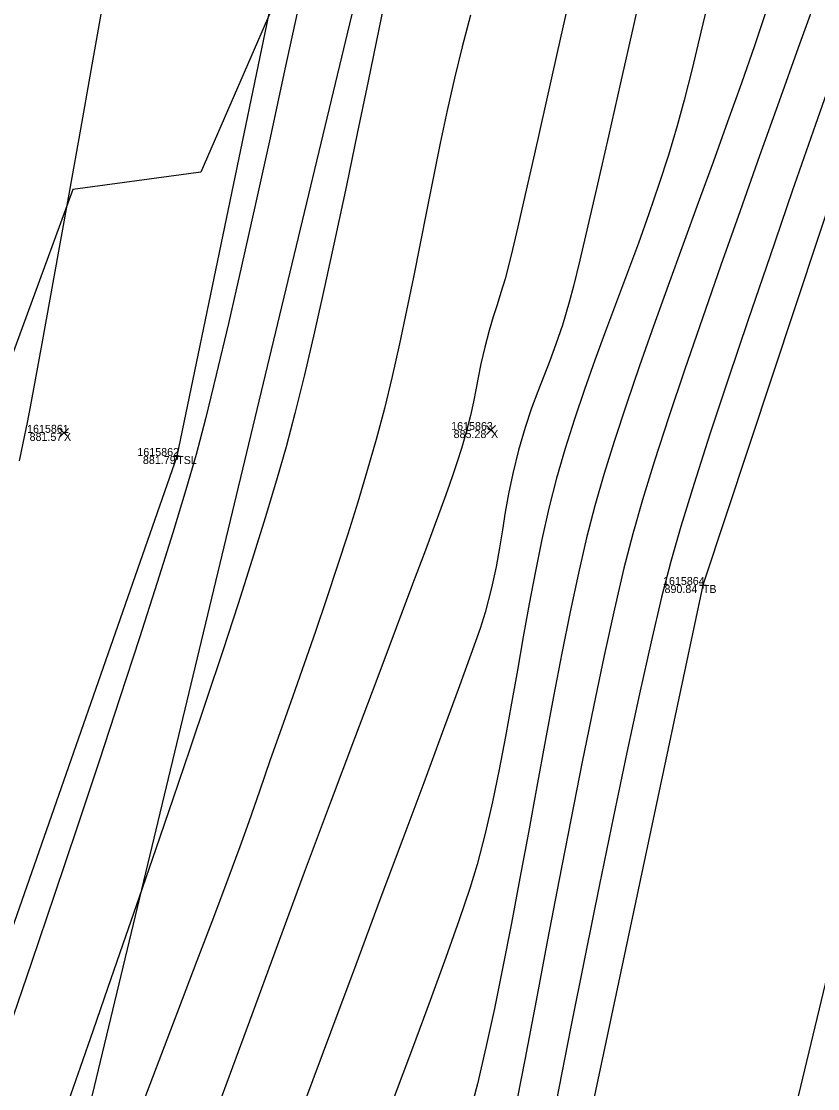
# Model space of a CAD drawing. Extents: x 1957117 to 1971063, y 701601 to 715861.
# Drawn here: x 1963015.01 to 1963049.81, y 704899.84 to 704946.5 of the extents above; entities that cross this region are included whole.
import ezdxf

# ---------------------------------------------------------------- set-up
doc = ezdxf.new("R2010")
doc.units = 0
for name, color, linetype in [('AP_X_Lights', 7, 'Continuous'), ('DT_X_Break_Line', 7, 'Continuous'), ('DT_X_Contour_Major', 7, 'Continuous'), ('DT_X_Contour_Minor', 7, 'Continuous'), ('GE_X_CL_20', 7, 'Continuous'), ('HY_X_Water_Edge', 7, 'Continuous'), ('PV_P_Drive', 7, 'Continuous'), ('PV_P_Shoulder', 7, 'Continuous'), ('RS_Raster1', 7, 'Continuous'), ('RW_X_Esmt_RR', 7, 'Continuous'), ('SC_Scratch1', 7, 'Continuous'), ('SC_Shading5', 7, 'Continuous'), ('VG_X_Tree_Line_Rt', 7, 'Continuous')]:
    doc.layers.add(name, color=color, linetype=linetype)

msp = doc.modelspace()

# ---------------------------------------------------------------- linework, layer by layer
at = {"layer": 'AP_X_Lights'}
for p, q in [((1963035.344, 704928.437), (1963035.732, 704928.827)), ((1963035.344, 704928.827), (1963035.732, 704928.437)), ((1963016.679, 704928.315), (1963017.067, 704928.705)), ((1963016.679, 704928.705), (1963017.067, 704928.315))]:
    msp.add_line(p, q, dxfattribs=at)
at = {"layer": 'DT_X_Break_Line'}
for points in [[(1962854.549, 704243.654), (1962868.069, 704295.231), (1962879.669, 704344.313), (1962892.757, 704392.318), (1962905.964, 704443.142), (1962917.718, 704492.375), (1962926.962, 704538.336), (1962936.778, 704587.265), (1962949.215, 704630.669), (1962963.968, 704683.754), (1962972.038, 704733.348), (1962988.206, 704780.999), (1962994.689, 704830.943), (1963004.932, 704879.138), (1963021.822, 704927.498), (1963031.944, 704976.286), (1963045.21, 705027.355), (1963059.618, 705072.384), (1963067.267, 705121.949)], [(1963081.686, 705067.168), (1963070.617, 705018.992), (1963060.629, 704969.66), (1963044.793, 704921.859), (1963033.624, 704869.219), (1963022.038, 704824.561), (1963012.554, 704778.141), (1962998.858, 704727.004), (1962987.967, 704677.611), (1962975.675, 704626.305), (1962966.447, 704580.213), (1962950.262, 704533.092), (1962939.515, 704481.257), (1962926.044, 704436.037), (1962917.68, 704386.811), (1962906.11, 704337.415), (1962892.064, 704289.931), (1962881.011, 704234.451)]]:
    msp.add_lwpolyline(points, dxfattribs=at)
at = {"layer": 'DT_X_Contour_Major'}
for points in [[(1963038.998, 704947.677), (1963038.428, 704945.137), (1963037.902, 704942.798), (1963037.432, 704940.713), (1963037.029, 704938.936), (1963036.706, 704937.52), (1963036.475, 704936.52), (1963036.348, 704935.989), (1963036.148, 704935.246), (1963035.969, 704934.641), (1963035.801, 704934.108), (1963035.635, 704933.578), (1963035.459, 704932.983), (1963035.265, 704932.255), (1963035.091, 704931.525), (1963034.969, 704930.927), (1963034.87, 704930.395), (1963034.769, 704929.864), (1963034.639, 704929.268), (1963034.452, 704928.542), (1963034.246, 704927.821), (1963034.063, 704927.239), (1963033.888, 704926.726), (1963033.705, 704926.215), (1963033.497, 704925.638), (1963033.248, 704924.928), (1963033.059, 704924.414), (1963032.673, 704923.385), (1963032.111, 704921.893), (1963031.392, 704919.99), (1963030.539, 704917.726), (1963029.571, 704915.152), (1963028.51, 704912.321), (1963027.376, 704909.284), (1963026.191, 704906.091), (1963024.975, 704902.795), (1963023.749, 704899.446)], [(1963038.998, 704947.677), (1963038.428, 704945.137), (1963037.902, 704942.798), (1963037.432, 704940.713), (1963037.029, 704938.936), (1963036.706, 704937.52), (1963036.475, 704936.52), (1963036.348, 704935.989), (1963036.148, 704935.246), (1963035.969, 704934.641), (1963035.801, 704934.108), (1963035.635, 704933.578), (1963035.459, 704932.983), (1963035.265, 704932.255), (1963035.091, 704931.525), (1963034.969, 704930.927), (1963034.87, 704930.395), (1963034.769, 704929.864), (1963034.639, 704929.268), (1963034.452, 704928.542), (1963034.246, 704927.821), (1963034.063, 704927.239), (1963033.888, 704926.726), (1963033.705, 704926.215), (1963033.497, 704925.638), (1963033.248, 704924.928), (1963033.059, 704924.414), (1963032.673, 704923.385), (1963032.111, 704921.893), (1963031.392, 704919.99), (1963030.539, 704917.726), (1963029.571, 704915.152), (1963028.51, 704912.321), (1963027.376, 704909.284), (1963026.191, 704906.091), (1963024.975, 704902.795), (1963023.749, 704899.446)], [(1963050.748, 704944.928), (1963049.719, 704941.992), (1963048.702, 704939.071), (1963047.715, 704936.211), (1963046.775, 704933.457), (1963045.899, 704930.856), (1963045.105, 704928.452), (1963044.411, 704926.292), (1963043.834, 704924.421), (1963043.392, 704922.885), (1963042.99, 704921.322), (1963042.53, 704919.376), (1963042.021, 704917.097), (1963041.469, 704914.535), (1963040.885, 704911.741), (1963040.275, 704908.766), (1963039.648, 704905.66), (1963039.013, 704902.474), (1963038.379, 704899.258)], [(1963050.748, 704944.928), (1963049.719, 704941.992), (1963048.702, 704939.071), (1963047.715, 704936.211), (1963046.775, 704933.457), (1963045.899, 704930.856), (1963045.105, 704928.452), (1963044.411, 704926.292), (1963043.834, 704924.421), (1963043.392, 704922.885), (1963042.99, 704921.322), (1963042.53, 704919.376), (1963042.021, 704917.097), (1963041.469, 704914.535), (1963040.885, 704911.741), (1963040.275, 704908.766), (1963039.648, 704905.66), (1963039.013, 704902.474), (1963038.379, 704899.258)]]:
    msp.add_lwpolyline(points, dxfattribs=at)
at = {"layer": 'DT_X_Contour_Minor'}
for points in [[(1963042.348, 704948.975), (1963041.756, 704946.324), (1963041.191, 704943.809), (1963040.665, 704941.479), (1963040.186, 704939.379), (1963039.765, 704937.556), (1963039.413, 704936.058), (1963039.14, 704934.93), (1963038.955, 704934.22), (1963038.657, 704933.224), (1963038.375, 704932.389), (1963038.104, 704931.662), (1963037.84, 704930.987), (1963037.576, 704930.313), (1963037.308, 704929.585), (1963037.032, 704928.749), (1963036.742, 704927.751), (1963036.485, 704926.734), (1963036.298, 704925.844), (1963036.156, 704925.037), (1963036.035, 704924.267), (1963035.911, 704923.489), (1963035.76, 704922.659), (1963035.558, 704921.73), (1963035.281, 704920.657), (1963035.058, 704919.959), (1963034.658, 704918.82), (1963034.102, 704917.285), (1963033.407, 704915.401), (1963032.593, 704913.211), (1963031.678, 704910.761), (1963030.681, 704908.095), (1963029.622, 704905.259), (1963028.518, 704902.298), (1963027.39, 704899.256)], [(1963042.348, 704948.975), (1963041.756, 704946.324), (1963041.191, 704943.809), (1963040.665, 704941.479), (1963040.186, 704939.379), (1963039.765, 704937.556), (1963039.413, 704936.058), (1963039.14, 704934.93), (1963038.955, 704934.22), (1963038.657, 704933.224), (1963038.375, 704932.389), (1963038.104, 704931.662), (1963037.84, 704930.987), (1963037.576, 704930.313), (1963037.308, 704929.585), (1963037.032, 704928.749), (1963036.742, 704927.751), (1963036.485, 704926.734), (1963036.298, 704925.844), (1963036.156, 704925.037), (1963036.035, 704924.267), (1963035.911, 704923.489), (1963035.76, 704922.659), (1963035.558, 704921.73), (1963035.281, 704920.657), (1963035.058, 704919.959), (1963034.658, 704918.82), (1963034.102, 704917.285), (1963033.407, 704915.401), (1963032.593, 704913.211), (1963031.678, 704910.761), (1963030.681, 704908.095), (1963029.622, 704905.259), (1963028.518, 704902.298), (1963027.39, 704899.256)], [(1963031.088, 704948.367), (1963030.633, 704946.157), (1963030.166, 704943.89), (1963029.691, 704941.602), (1963029.214, 704939.328), (1963028.74, 704937.1), (1963028.273, 704934.956), (1963027.819, 704932.928), (1963027.383, 704931.051), (1963026.969, 704929.361), (1963026.583, 704927.892), (1963026.168, 704926.437), (1963025.671, 704924.789), (1963025.105, 704922.976), (1963024.48, 704921.029), (1963023.809, 704918.978), (1963023.103, 704916.853), (1963022.374, 704914.683), (1963021.632, 704912.499), (1963020.89, 704910.33), (1963020.159, 704908.206), (1963019.451, 704906.157), (1963018.776, 704904.214), (1963018.147, 704902.405), (1963017.576, 704900.761), (1963017.073, 704899.312)], [(1963031.088, 704948.367), (1963030.633, 704946.157), (1963030.166, 704943.89), (1963029.691, 704941.602), (1963029.214, 704939.328), (1963028.74, 704937.1), (1963028.273, 704934.956), (1963027.819, 704932.928), (1963027.383, 704931.051), (1963026.969, 704929.361), (1963026.583, 704927.892), (1963026.168, 704926.437), (1963025.671, 704924.789), (1963025.105, 704922.976), (1963024.48, 704921.029), (1963023.809, 704918.978), (1963023.103, 704916.853), (1963022.374, 704914.683), (1963021.632, 704912.499), (1963020.89, 704910.33), (1963020.159, 704908.206), (1963019.451, 704906.157), (1963018.776, 704904.214), (1963018.147, 704902.405), (1963017.576, 704900.761), (1963017.073, 704899.312)], [(1963027.192, 704947.483), (1963026.532, 704944.41), (1963025.879, 704941.405), (1963025.243, 704938.517), (1963024.634, 704935.796), (1963024.06, 704933.29), (1963023.532, 704931.051), (1963023.058, 704929.126), (1963022.648, 704927.566), (1963022.205, 704926.021), (1963021.634, 704924.14), (1963020.952, 704921.967), (1963020.176, 704919.548), (1963019.322, 704916.929), (1963018.406, 704914.155), (1963017.445, 704911.272), (1963016.456, 704908.324), (1963015.454, 704905.358), (1963014.455, 704902.419), (1963013.477, 704899.551)], [(1963027.192, 704947.483), (1963026.532, 704944.41), (1963025.879, 704941.405), (1963025.243, 704938.517), (1963024.634, 704935.796), (1963024.06, 704933.29), (1963023.532, 704931.051), (1963023.058, 704929.126), (1963022.648, 704927.566), (1963022.205, 704926.021), (1963021.634, 704924.14), (1963020.952, 704921.967), (1963020.176, 704919.548), (1963019.322, 704916.929), (1963018.406, 704914.155), (1963017.445, 704911.272), (1963016.456, 704908.324), (1963015.454, 704905.358), (1963014.455, 704902.419), (1963013.477, 704899.551)], [(1963014.937, 704927.292), (1963015.096, 704928.056), (1963015.279, 704928.959), (1963015.412, 704929.655), (1963015.628, 704930.825), (1963015.917, 704932.413), (1963016.269, 704934.36), (1963016.675, 704936.61), (1963017.123, 704939.105), (1963017.604, 704941.788), (1963018.107, 704944.601), (1963018.623, 704947.488)], [(1963014.937, 704927.292), (1963015.096, 704928.056), (1963015.279, 704928.959), (1963015.412, 704929.655), (1963015.628, 704930.825), (1963015.917, 704932.413), (1963016.269, 704934.36), (1963016.675, 704936.61), (1963017.123, 704939.105), (1963017.604, 704941.788), (1963018.107, 704944.601), (1963018.623, 704947.488)], [(1963045.126, 704947.812), (1963044.706, 704946.02), (1963044.32, 704944.421), (1963043.974, 704943.049), (1963043.675, 704941.938), (1963043.293, 704940.647), (1963042.877, 704939.361), (1963042.436, 704938.078), (1963041.976, 704936.797), (1963041.503, 704935.518), (1963041.024, 704934.239), (1963040.546, 704932.961), (1963040.075, 704931.681), (1963039.619, 704930.399), (1963039.184, 704929.115), (1963038.777, 704927.827), (1963038.404, 704926.535), (1963038.067, 704925.216), (1963037.759, 704923.854), (1963037.473, 704922.458), (1963037.204, 704921.036), (1963036.945, 704919.594), (1963036.691, 704918.142), (1963036.436, 704916.686), (1963036.173, 704915.236), (1963035.896, 704913.799), (1963035.6, 704912.382), (1963035.279, 704910.994), (1963034.926, 704909.643), (1963034.604, 704908.587), (1963034.143, 704907.22), (1963033.561, 704905.578), (1963032.874, 704903.698), (1963032.101, 704901.618), (1963031.258, 704899.374)], [(1963045.126, 704947.812), (1963044.706, 704946.02), (1963044.32, 704944.421), (1963043.974, 704943.049), (1963043.675, 704941.938), (1963043.293, 704940.647), (1963042.877, 704939.361), (1963042.436, 704938.078), (1963041.976, 704936.797), (1963041.503, 704935.518), (1963041.024, 704934.239), (1963040.546, 704932.961), (1963040.075, 704931.681), (1963039.619, 704930.399), (1963039.184, 704929.115), (1963038.777, 704927.827), (1963038.404, 704926.535), (1963038.067, 704925.216), (1963037.759, 704923.854), (1963037.473, 704922.458), (1963037.204, 704921.036), (1963036.945, 704919.594), (1963036.691, 704918.142), (1963036.436, 704916.686), (1963036.173, 704915.236), (1963035.896, 704913.799), (1963035.6, 704912.382), (1963035.279, 704910.994), (1963034.926, 704909.643), (1963034.604, 704908.587), (1963034.143, 704907.22), (1963033.561, 704905.578), (1963032.874, 704903.698), (1963032.101, 704901.618), (1963031.258, 704899.374)], [(1963049.772, 704947.603), (1963048.964, 704945.346), (1963048.126, 704943.004), (1963047.273, 704940.615), (1963046.419, 704938.214), (1963045.581, 704935.837), (1963044.773, 704933.521), (1963044.011, 704931.3), (1963043.311, 704929.212), (1963042.687, 704927.292), (1963042.154, 704925.577), (1963041.729, 704924.101), (1963041.344, 704922.6), (1963040.926, 704920.81), (1963040.479, 704918.773), (1963040.01, 704916.532), (1963039.523, 704914.126), (1963039.023, 704911.598), (1963038.517, 704908.99), (1963038.008, 704906.343), (1963037.503, 704903.698), (1963037.007, 704901.097), (1963036.525, 704898.582)], [(1963049.772, 704947.603), (1963048.964, 704945.346), (1963048.126, 704943.004), (1963047.273, 704940.615), (1963046.419, 704938.214), (1963045.581, 704935.837), (1963044.773, 704933.521), (1963044.011, 704931.3), (1963043.311, 704929.212), (1963042.687, 704927.292), (1963042.154, 704925.577), (1963041.729, 704924.101), (1963041.344, 704922.6), (1963040.926, 704920.81), (1963040.479, 704918.773), (1963040.01, 704916.532), (1963039.523, 704914.126), (1963039.023, 704911.598), (1963038.517, 704908.99), (1963038.008, 704906.343), (1963037.503, 704903.698), (1963037.007, 704901.097), (1963036.525, 704898.582)], [(1963047.561, 704946.955), (1963047.045, 704945.425), (1963046.479, 704943.801), (1963045.873, 704942.103), (1963045.239, 704940.349), (1963044.587, 704938.56), (1963043.929, 704936.755), (1963043.275, 704934.954), (1963042.637, 704933.176), (1963042.025, 704931.441), (1963041.451, 704929.768), (1963040.926, 704928.177), (1963040.461, 704926.687), (1963040.067, 704925.318), (1963039.71, 704923.927), (1963039.352, 704922.374), (1963038.992, 704920.684), (1963038.63, 704918.882), (1963038.266, 704916.991), (1963037.902, 704915.037), (1963037.535, 704913.044), (1963037.168, 704911.036), (1963036.799, 704909.037), (1963036.43, 704907.074), (1963036.059, 704905.169), (1963035.688, 704903.347), (1963035.316, 704901.634), (1963034.944, 704900.053), (1963034.571, 704898.628)], [(1963047.561, 704946.955), (1963047.045, 704945.425), (1963046.479, 704943.801), (1963045.873, 704942.103), (1963045.239, 704940.349), (1963044.587, 704938.56), (1963043.929, 704936.755), (1963043.275, 704934.954), (1963042.637, 704933.176), (1963042.025, 704931.441), (1963041.451, 704929.768), (1963040.926, 704928.177), (1963040.461, 704926.687), (1963040.067, 704925.318), (1963039.71, 704923.927), (1963039.352, 704922.374), (1963038.992, 704920.684), (1963038.63, 704918.882), (1963038.266, 704916.991), (1963037.902, 704915.037), (1963037.535, 704913.044), (1963037.168, 704911.036), (1963036.799, 704909.037), (1963036.43, 704907.074), (1963036.059, 704905.169), (1963035.688, 704903.347), (1963035.316, 704901.634), (1963034.944, 704900.053), (1963034.571, 704898.628)], [(1963034.641, 704946.775), (1963034.275, 704945.383), (1963033.94, 704944.011), (1963033.621, 704942.605), (1963033.315, 704941.174), (1963033.018, 704939.722), (1963032.726, 704938.258), (1963032.436, 704936.788), (1963032.143, 704935.318), (1963031.844, 704933.856), (1963031.536, 704932.408), (1963031.214, 704930.981), (1963030.876, 704929.582), (1963030.517, 704928.217), (1963030.131, 704926.859), (1963029.717, 704925.478), (1963029.278, 704924.08), (1963028.82, 704922.669), (1963028.345, 704921.25), (1963027.86, 704919.829), (1963027.367, 704918.409), (1963026.872, 704916.996), (1963026.378, 704915.594), (1963025.89, 704914.209), (1963025.412, 704912.845), (1963024.949, 704911.508), (1963024.558, 704910.408), (1963024.037, 704909.003), (1963023.406, 704907.328), (1963022.68, 704905.422), (1963021.877, 704903.321), (1963021.014, 704901.063), (1963020.11, 704898.685)], [(1963034.641, 704946.775), (1963034.275, 704945.383), (1963033.94, 704944.011), (1963033.621, 704942.605), (1963033.315, 704941.174), (1963033.018, 704939.722), (1963032.726, 704938.258), (1963032.436, 704936.788), (1963032.143, 704935.318), (1963031.844, 704933.856), (1963031.536, 704932.408), (1963031.214, 704930.981), (1963030.876, 704929.582), (1963030.517, 704928.217), (1963030.131, 704926.859), (1963029.717, 704925.478), (1963029.278, 704924.08), (1963028.82, 704922.669), (1963028.345, 704921.25), (1963027.86, 704919.829), (1963027.367, 704918.409), (1963026.872, 704916.996), (1963026.378, 704915.594), (1963025.89, 704914.209), (1963025.412, 704912.845), (1963024.949, 704911.508), (1963024.558, 704910.408), (1963024.037, 704909.003), (1963023.406, 704907.328), (1963022.68, 704905.422), (1963021.877, 704903.321), (1963021.014, 704901.063), (1963020.11, 704898.685)]]:
    msp.add_lwpolyline(points, dxfattribs=at)
at = {"layer": 'GE_X_CL_20'}
msp.add_lwpolyline([(1963418.3, 706437.397), (1962895.621, 704261.062)], dxfattribs=at)
at = {"layer": 'HY_X_Water_Edge'}
msp.add_spline([(1963191.723, 701994.048), (1963062.047, 702441.167), (1962863.491, 703169.356), (1962827.53, 703438.691), (1962823.213, 703537.412), (1962817.962, 703593.874), (1962817.97, 703697.316), (1962828.582, 703804.235), (1962836.461, 703844.734), (1962850.687, 703896.004), (1962867.251, 703938.846), (1962873.848, 703992.355), (1962884.135, 704091.371), (1962891.241, 704140.854), (1962897.382, 704180.529), (1962905.467, 704230.979), (1962943.949, 704328.022), (1962948.537, 704378.842), (1962964.114, 704426.264), (1963004.885, 704570.73), (1963042.054, 704716.522), (1963062.038, 704814.417), (1963072.171, 704860.237), (1963090.023, 704956.798), (1963107.066, 705031.783), (1963133.773, 705105.742), (1963148.685, 705206.74), (1963175.48, 705301.059), (1963191.635, 705353.417), (1963210.988, 705447.286), (1963219.532, 705497.27), (1963230.124, 705549.475), (1963251.052, 705591.159), (1963275.289, 705693.429), (1963292.982, 705784.032), (1963302.841, 705839.645), (1963335.126, 705936.766), (1963359.752, 706046.75), (1963389.133, 706177.299), (1963417.827, 706273.456), (1963475.868, 706451.902), (1963533.782, 706640.53), (1963553.86, 706696.984), (1963580.184, 706715.425), (1963609.172, 706718.73), (1963617.062, 706714.691), (1963619.447, 706694.678), (1963564.282, 706533.07), (1963531.853, 706395.229), (1963434.4, 706006.96), (1963354.09, 705679.186), (1963237.513, 705206.07), (1963167.369, 704892.962), (1963059.145, 704434.176), (1962907.914, 703908.742), (1962877.458, 703703.326), (1962898.357, 703412.121), (1962942.65, 703052.267), (1963048.963, 702674.866), (1963191.468, 702189.666), (1963245.396, 702019.832)], degree=3, dxfattribs=at)
at = {"layer": 'PV_P_Drive'}
for p, q in [((1963021.676, 704927.498), (1963021.968, 704927.498)), ((1963021.822, 704927.644), (1963021.822, 704927.352)), ((1963021.822, 704927.498), (1963021.822, 704927.498)), ((1963044.647, 704921.859), (1963044.939, 704921.859)), ((1963044.793, 704922.005), (1963044.793, 704921.713)), ((1963044.793, 704921.859), (1963044.793, 704921.859))]:
    msp.add_line(p, q, dxfattribs=at)
at = {"layer": 'RW_X_Esmt_RR'}
msp.add_lwpolyline([(1962866.45, 704268.068), (1963123.345, 705337.727), (1963135.496, 705336.937), (1963400.797, 706441.601)], dxfattribs=at)
at = {"layer": 'SC_Shading5'}
for points in [[(1963026.912, 704294.121), (1963138.818, 704737.794), (1963251.679, 705213.963), (1963374.306, 705730.111), (1963454.783, 706045.593), (1963517.244, 706296.713), (1963562.763, 706479.256), (1963580.13, 706553.799), (1963589.678, 706586.994)], [(1963609.915, 706579.703), (1963587.283, 706499.153), (1963552.056, 706354.005), (1963480.911, 706069.234), (1963357.401, 705576.869), (1963272.751, 705226.931), (1963210.247, 704956.481), (1963044.97, 704288.881)]]:
    msp.add_spline(points, degree=3, dxfattribs=at)
at = {"layer": 'VG_X_Tree_Line_Rt'}
msp.add_lwpolyline([(1963026.502, 704948.305), (1963022.857, 704939.902), (1963017.256, 704939.146), (1963013.262, 704928.256), (1963013.507, 704918.028), (1963010.148, 704906.744), (1963006, 704905.059), (1963002.407, 704900.162), (1962999.232, 704891.585), (1962997.468, 704882.662), (1963007.109, 704876.853), (1963008.813, 704864.175), (1963004.594, 704851.399)], dxfattribs=at)

# ---------------------------------------------------------------- texts
at = {"layer": 'PV_P_Shoulder'}
for s, p in [('881.57', (1963015.371, 704928.16)), ('885.28', (1963033.901, 704928.282)), ('881.79', (1963020.323, 704927.148)), ('890.84', (1963043.118, 704921.509))]:
    msp.add_text(s, height=0.35, dxfattribs=at).set_placement(p)
at = {"layer": 'RS_Raster1'}
for s, p in [('1615861', (1963015.261, 704928.51)), ('1615863', (1963033.794, 704928.632)), ('1615862', (1963020.081, 704927.498)), ('1615864', (1963043.052, 704921.859))]:
    msp.add_text(s, height=0.35, dxfattribs=at).set_placement(p)
at = {"layer": 'SC_Scratch1'}
for s, p in [('X', (1963016.873, 704928.16)), ('X', (1963035.538, 704928.282)), ('TSL', (1963021.822, 704927.148)), ('TB', (1963044.793, 704921.509))]:
    msp.add_text(s, height=0.35, dxfattribs=at).set_placement(p)

doc.saveas('drawing.dxf')
